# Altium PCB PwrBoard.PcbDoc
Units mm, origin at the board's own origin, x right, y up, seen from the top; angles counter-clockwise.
Board outline 35 x 15 mm, 2 copper layers (Top Layer, Bottom Layer); 5 components, 3 nets, 10 pads, 0 vias.
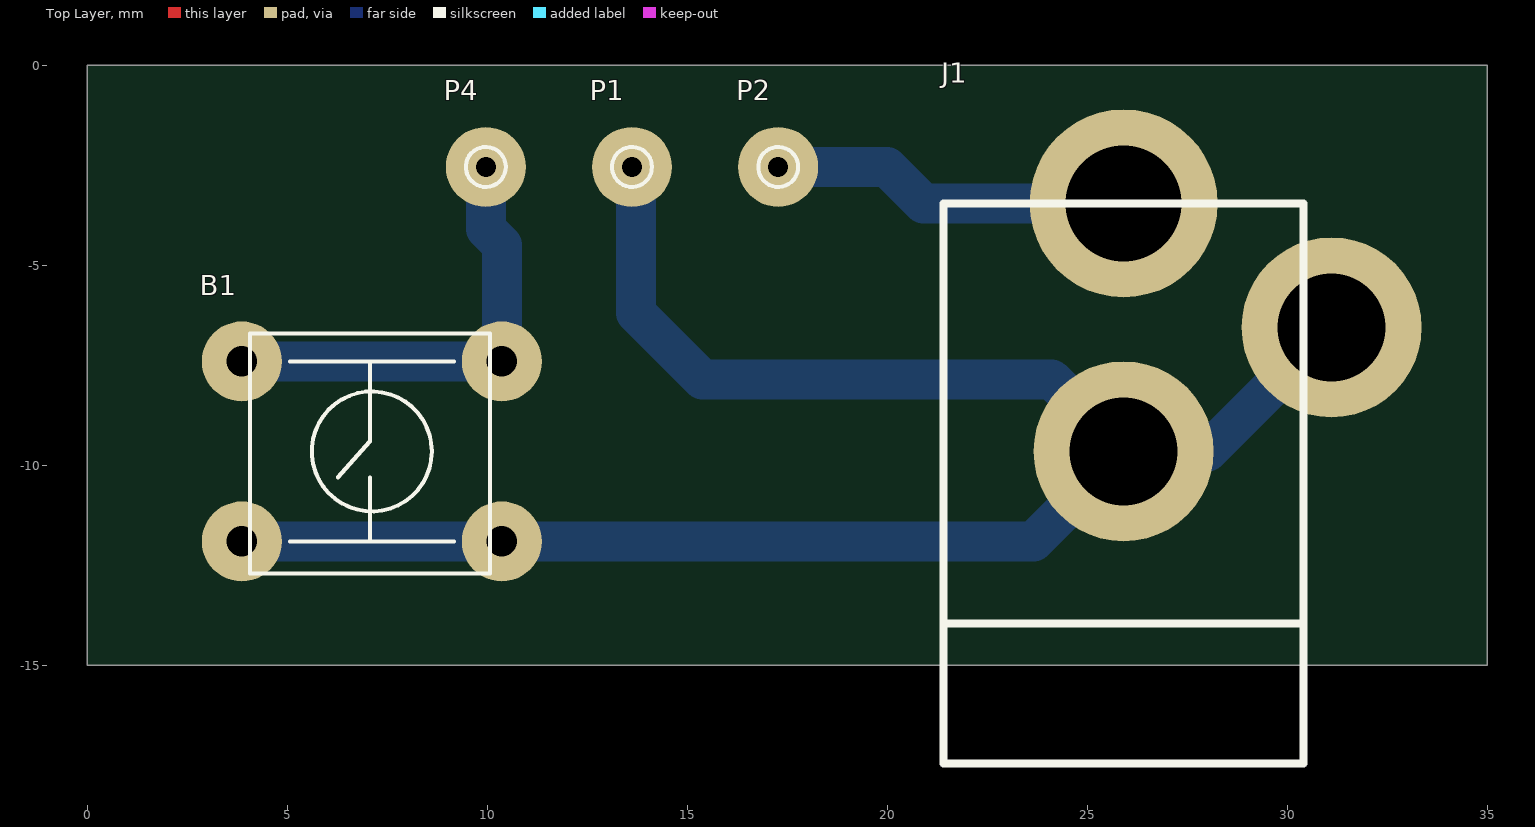
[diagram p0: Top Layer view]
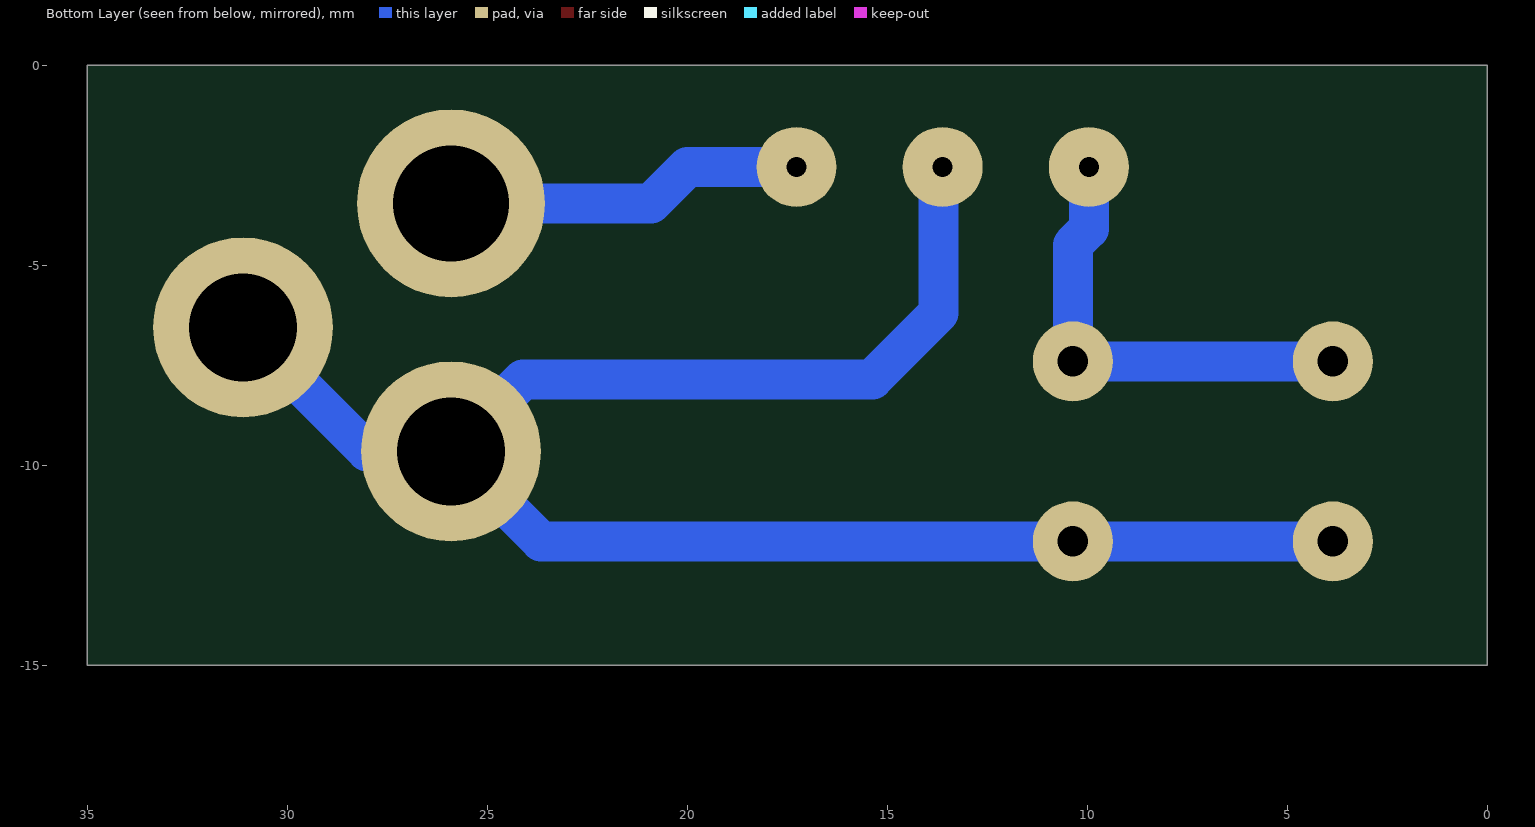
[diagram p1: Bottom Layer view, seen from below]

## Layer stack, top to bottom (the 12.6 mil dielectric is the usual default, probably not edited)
Top Layer: signal copper 0.0356
Dielectric: dielectric 0.32, FR-4, Dk 4.8
Bottom Layer: signal copper 0.0356

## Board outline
0,-15 35,-15 35,0 0,0

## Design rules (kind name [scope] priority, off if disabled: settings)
Clearance "GND Polygon" [InNet('GND') And InPolygon] p1: gap=1
Clearance [All] p2: gap=0.2
ComponentClearance [All] p1: gap=0.2 collisioncheckmode=3 verticalgap=2540 showdistances=FALSE
Height [All] p1: minheight=0 maxheight=100 prefheight=12.7
HoleSize [All] p1: absolutevalues=TRUE maxlimit=5 minlimit=0.5 maxpercent=80.000 minpercent=20.000
HoleSize Testpoint [All] p2: absolutevalues=TRUE maxlimit=2.54 minlimit=0.025 maxpercent=80.000 minpercent=20.000
HoleSize TestPointUsage [All] p3: absolutevalues=TRUE maxlimit=2.54 minlimit=0.025 maxpercent=80.000 minpercent=20.000
MinimumSolderMaskSliver [All] p1: minsoldermaskwidth=0
NetAntennae [All and not InNet('GND')] p1: netantennaetolerance=0
PlaneClearance [All] p1: clearance=1
PolygonConnect [All] p1: connectstyle=Relief reliefconductorwidth=1 reliefentries=4 polygonreliefangle="90 Angle"
RoutingVias [All] p1: holewidth=0.5 width=1.5 viastyle="Through Hole" minholewidth=0.5 minwidth=1.5 maxholewidth=0.5 maxwidth=1.5
SilkToSilkClearance [All] p1: silktosilkclearance=0
SilkscreenOverComponentPads [All] p1: minsilkscreentomaskgap=0
SolderMaskExpansion [All] p1: expansion=0.102
Width [All] p1: maxlimit=2 minlimit=0.3 preferedwidth=0.5
20 further rules are at their usual default settings.

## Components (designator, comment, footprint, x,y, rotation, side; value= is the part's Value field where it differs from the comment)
B1 "BUTTON" BUTTON 7.112,-9.652 r180 top
J1 "DJK-02A" DJK-02A 25.908,-3.452 r90 top
P1 "-Vcc" "Pin 2.0x0.5" 13.617,-2.54 r0 top
P2 "+Vcc" "Pin 2.0x0.5" 17.272,-2.54 r0 top
P4 "Button" "Pin 2.0x0.5" 9.962,-2.54 r0 top

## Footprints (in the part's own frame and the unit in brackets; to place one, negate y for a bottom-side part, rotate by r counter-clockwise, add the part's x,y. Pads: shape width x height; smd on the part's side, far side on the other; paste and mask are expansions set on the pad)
BUTTON [mm]
  round 2 hole 0.762: 1(-3.25,2.25) 2(3.25,2.25) 3(-3.25,-2.25) 4(3.25,-2.25)
  silkscreen extent -2.95,-2.95 3.05,3.05
DJK-02A [mm] "LowPower Jack 2.0mm connector"
  round 4.7 hole 2.9: 1(0,0)
  round 4.5 hole 2.7: 2(-6.2,0) 3(-3.1,-5.2)
  silkscreen extent -14,-4.5 0,4.5, body extent -13.7,-4.9 0.78,4.57, height 11.18
"Pin 2.0x0.5" [mm]
  round 2 hole 0.5: 1(0,0)
  silkscreen extent -0.5,-0.5 0.5,0.5

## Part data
B1: library part BUTTON_TACT
J1: "Low Voltage Power Supply Connector"
P1 P2 P4: library part Pin

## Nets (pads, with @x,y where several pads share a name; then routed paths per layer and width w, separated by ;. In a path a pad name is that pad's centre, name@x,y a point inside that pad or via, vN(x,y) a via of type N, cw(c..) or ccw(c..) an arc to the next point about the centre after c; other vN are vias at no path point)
NetB1_1: B1.1 B1.2 J1.2 J1.3 P1.1 | length 46.7
  Bottom Layer w1: B1.2 B1.1 23.658,-11.902 J1.2 ; P1.1@13.716,-2.54 13.716,-6.191 15.375,-7.85 24.106,-7.85 J1.2 ; J1.3 28.008,-9.652 J1.2
NetB1_3: B1.3 B1.4 P4.1 | length 11.5
  Bottom Layer w1: B1.4 B1.3 10.362,-4.487 9.962,-4.087 P4.1
NetJ1_1: J1.1 P2.1 | length 9
  Bottom Layer w1: P2.1 19.99,-2.54 20.902,-3.452 J1.1

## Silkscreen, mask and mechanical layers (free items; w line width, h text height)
outline:
  the board outline again, w0.2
